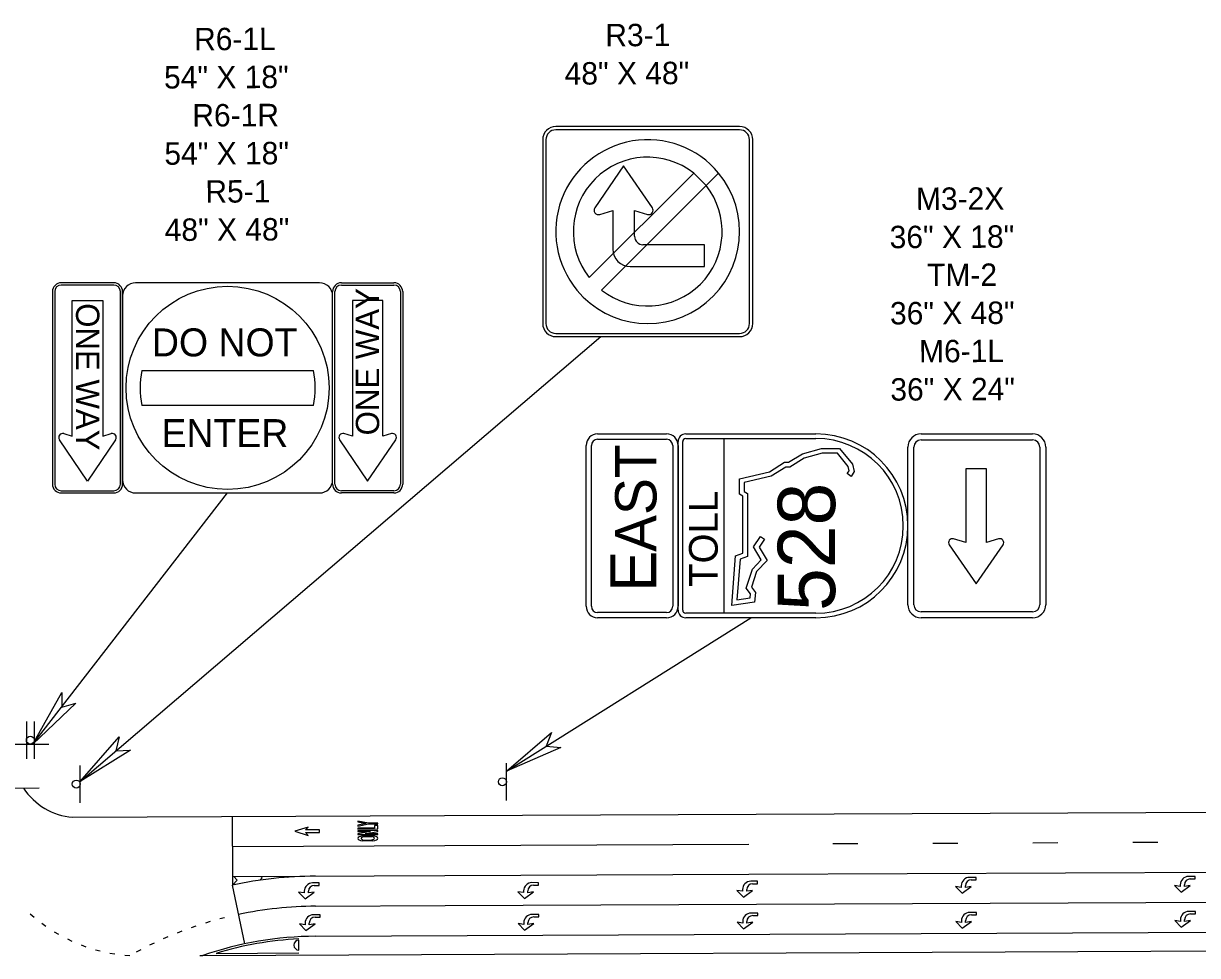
# Model space of a CAD drawing. Extents: x 582908 to 586039, y 1530940 to 1532988.
# Drawn here: x 583736 to 584469, y 1532406 to 1532988 of the extents above; entities that cross this region are included whole.
import ezdxf

# ---------------------------------------------------------------- set-up
doc = ezdxf.new("R2010")
doc.units = 0
for name, color, linetype in [('DirArrowsPavt', 7, 'Continuous'), ('LeaderLine_dp', 7, 'Continuous'), ('PavtMessage', 7, 'Continuous'), ('PMStripe12W', 7, 'Continuous'), ('PMStripe18W', 7, 'Continuous'), ('PMStripe24W', 7, 'Continuous'), ('PMStripe6W', 7, 'Continuous'), ('PMStripe6W(10-30)', 7, 'Continuous'), ('PMStripe6W(2-4)', 7, 'Continuous'), ('PMStripe6Y', 7, 'Continuous'), ('PMStripe6Y(2-4)', 7, 'Continuous'), ('PMStripe8W', 7, 'Continuous'), ('SignPanel', 7, 'Continuous'), ('SignSupport', 7, 'Continuous'), ('TextLabel', 7, 'Continuous')]:
    doc.layers.add(name, color=color, linetype=linetype)

msp = doc.modelspace()

# ---------------------------------------------------------------- linework, layer by layer
at = {"layer": 'DirArrowsPavt'}
for p, q in [((583913.26, 1532486.2), (583905.07, 1532483.56)), ((583911.71, 1532484.37), (583913.26, 1532486.2)), ((583920.43, 1532484.41), (583911.71, 1532484.37)), ((583920.44, 1532482.85), (583920.43, 1532484.41)), ((583905.07, 1532483.56), (583913.28, 1532480.99)), ((583911.71, 1532482.81), (583920.44, 1532482.85)), ((583913.28, 1532480.99), (583911.71, 1532482.81))]:
    msp.add_line(p, q, dxfattribs=at)
for points in [[(584327.57, 1532453.21), (584330.7, 1532453.2), (584330.7, 1532454.77), (584326.53, 1532454.77)], [(584464.38, 1532453.82), (584467.5, 1532453.81), (584467.51, 1532455.37), (584463.34, 1532455.38)], [(583917.18, 1532449.72), (583920.31, 1532449.72), (583920.31, 1532451.28), (583916.15, 1532451.29)], [(584054.17, 1532449.89), (584057.29, 1532449.89), (584057.29, 1532451.45), (584053.13, 1532451.46)], [(584184.68, 1532447.12), (584184.68, 1532446.08), (584181.16, 1532446.6), (584185.19, 1532442.43)], [(584185.19, 1532442.43), (584190.93, 1532446.59), (584187.28, 1532446.07), (584187.28, 1532447.12)], [(584190.93, 1532450.75), (584194.06, 1532450.75), (584194.06, 1532452.31), (584189.9, 1532452.32)], [(584321.32, 1532449.57), (584321.32, 1532448.53), (584317.8, 1532449.06), (584321.83, 1532444.89)], [(584321.83, 1532444.89), (584327.57, 1532449.04), (584323.92, 1532448.53), (584323.92, 1532449.57)], [(584458.12, 1532450.18), (584458.12, 1532449.14), (584454.6, 1532449.67), (584458.63, 1532445.49)], [(584458.63, 1532445.49), (584464.37, 1532449.65), (584460.72, 1532449.13), (584460.73, 1532450.18)], [(583910.93, 1532446.09), (583910.93, 1532445.05), (583907.41, 1532445.57), (583911.44, 1532441.4)], [(583911.44, 1532441.4), (583917.18, 1532445.56), (583913.53, 1532445.04), (583913.53, 1532446.09)], [(584047.91, 1532446.26), (584047.91, 1532445.22), (584044.39, 1532445.74), (584048.42, 1532441.57)], [(584048.42, 1532441.57), (584054.16, 1532445.73), (584050.51, 1532445.21), (584050.51, 1532446.25)], [(584191.02, 1532430.92), (584194.15, 1532430.91), (584194.15, 1532432.48), (584189.98, 1532432.48)], [(584327.67, 1532431.35), (584330.8, 1532431.34), (584330.8, 1532432.9), (584326.63, 1532432.91)], [(584464.47, 1532431.95), (584467.6, 1532431.95), (584467.6, 1532433.51), (584463.44, 1532433.52)], [(583911.41, 1532426.25), (583911.4, 1532425.21), (583907.89, 1532425.74), (583911.92, 1532421.57)], [(583911.92, 1532421.57), (583917.65, 1532425.72), (583914.01, 1532425.21), (583914.01, 1532426.25)], [(583917.66, 1532429.89), (583920.79, 1532429.88), (583920.79, 1532431.45), (583916.62, 1532431.45)], [(584048, 1532426.42), (584048, 1532425.38), (584044.48, 1532425.91), (584048.51, 1532421.73)], [(584048.51, 1532421.73), (584054.25, 1532425.89), (584050.6, 1532425.38), (584050.6, 1532426.42)], [(584054.25, 1532430.06), (584057.38, 1532430.05), (584057.38, 1532431.61), (584053.21, 1532431.62)], [(584184.77, 1532427.28), (584184.76, 1532426.24), (584181.25, 1532426.77), (584185.28, 1532422.6)], [(584185.28, 1532422.6), (584191.02, 1532426.75), (584187.37, 1532426.24), (584187.37, 1532427.28)], [(584321.41, 1532427.71), (584321.41, 1532426.67), (584317.9, 1532427.2), (584321.93, 1532423.02)], [(584321.93, 1532423.02), (584327.66, 1532427.18), (584324.02, 1532426.66), (584324.02, 1532427.71)], [(584458.22, 1532428.32), (584458.22, 1532427.28), (584454.7, 1532427.8), (584458.73, 1532423.63)], [(584458.73, 1532423.63), (584464.47, 1532427.79), (584460.82, 1532427.27), (584460.82, 1532428.31)]]:
    msp.add_lwpolyline(points, dxfattribs=at)
for centre, radius in [((584326.53, 1532449.57), 5.21), ((584463.33, 1532450.17), 5.21), ((583916.14, 1532446.08), 5.21), ((583917.18, 1532446.08), 3.65), ((584053.12, 1532446.25), 5.21), ((584054.16, 1532446.25), 3.65), ((584189.89, 1532447.11), 5.21), ((584190.93, 1532447.11), 3.65), ((584327.57, 1532449.56), 3.65), ((584464.37, 1532450.17), 3.65), ((584189.97, 1532427.28), 5.21), ((584326.62, 1532427.7), 5.21), ((584463.43, 1532428.31), 5.21), ((583916.61, 1532426.24), 5.21), ((583917.66, 1532426.24), 3.65), ((584053.21, 1532426.41), 5.21), ((584054.25, 1532426.41), 3.65), ((584191.02, 1532427.27), 3.65), ((584327.66, 1532427.7), 3.65), ((584464.47, 1532428.31), 3.65)]:
    msp.add_arc(centre, radius, 89.90326, 179.90326, dxfattribs=at)
at = {"layer": 'LeaderLine_dp'}
for p, q in [((583770.98, 1532514.7), (584096.08, 1532792.5)), ((583741.46, 1532537.97), (583863.01, 1532694.88)), ((584037.19, 1532521.1), (584189.87, 1532616.9)), ((583741.46, 1532537.97), (583759.52, 1532570.24)), ((583759.52, 1532570.24), (583759.38, 1532561.1)), ((583768.2, 1532563.52), (583741.46, 1532537.97)), ((583759.38, 1532561.1), (583768.2, 1532563.52)), ((583770.98, 1532514.7), (583795.22, 1532542.63)), ((583795.22, 1532542.63), (583793.22, 1532533.71)), ((584037.19, 1532521.1), (584065.26, 1532545.19)), ((584065.26, 1532545.19), (584061.97, 1532536.65)), ((584071.09, 1532535.89), (584037.19, 1532521.1)), ((584061.97, 1532536.65), (584071.09, 1532535.89)), ((583802.35, 1532534.29), (583770.98, 1532514.7)), ((583793.22, 1532533.71), (583802.35, 1532534.29))]:
    msp.add_line(p, q, dxfattribs=at)
at = {"layer": 'PavtMessage'}
for p, q in [((583951.07, 1532488.65), (583944.29, 1532489.92)), ((583944.29, 1532489.92), (583944.3, 1532489.39)), ((583944.3, 1532489.39), (583949.67, 1532488.38)), ((583949.67, 1532488.38), (583944.31, 1532487.33)), ((583944.31, 1532486.8), (583951.07, 1532488.13)), ((583944.31, 1532487.33), (583944.31, 1532486.8)), ((583954.73, 1532485.54), (583944.31, 1532485.49)), ((583944.31, 1532485.49), (583944.32, 1532484.97)), ((583944.32, 1532484.97), (583956.82, 1532485.03)), ((583956.82, 1532483.99), (583944.32, 1532483.93)), ((583944.32, 1532483.93), (583944.32, 1532483.41)), ((583956.8, 1532488.67), (583951.07, 1532488.65)), ((583951.07, 1532488.13), (583956.8, 1532488.15)), ((583956.81, 1532487.11), (583954.72, 1532487.1)), ((583954.72, 1532487.1), (583954.73, 1532485.54)), ((583956.8, 1532488.15), (583956.8, 1532488.67)), ((583956.82, 1532485.03), (583956.81, 1532487.11)), ((583956.82, 1532483.47), (583956.82, 1532483.99)), ((583944.32, 1532483.41), (583952.29, 1532483.45)), ((583952.29, 1532483.45), (583944.33, 1532481.98)), ((583944.33, 1532481.98), (583944.33, 1532481.46)), ((583944.33, 1532481.46), (583956.83, 1532481.51)), ((583947.37, 1532480.69), (583953.8, 1532480.72)), ((583953.82, 1532477.59), (583947.38, 1532477.57)), ((583953.09, 1532480.19), (583948.09, 1532480.17)), ((583948.1, 1532478.09), (583953.1, 1532478.11)), ((583949.02, 1532482), (583956.82, 1532483.47)), ((583956.83, 1532482.03), (583949.02, 1532482)), ((583956.83, 1532481.51), (583956.83, 1532482.03))]:
    msp.add_line(p, q, dxfattribs=at)
for major_axis, ratio, start_param, end_param in [((-6.25, -0.03), 0.291667, 5.253489, 7.312882), ((-4.17, -0.02), 0.3125, 5.35589, 7.210481), ((-4.17, -0.02), 0.3125, 2.214297, 4.068888), ((-6.25, -0.03), 0.291667, 2.111896, 4.171289)]:
    msp.add_ellipse((583950.59, 1532479.14), major_axis=major_axis, ratio=ratio, start_param=start_param, end_param=end_param, dxfattribs=at)
at = {"layer": 'PMStripe12W'}
msp.add_line((583570.9, 1532509.82), (583745.38, 1532510.59), dxfattribs=at)
at = {"layer": 'PMStripe18W'}
for p, q in [((583866.83, 1532455.27), (583869.07, 1532453.05)), ((583883.2, 1532452.98), (583884.68, 1532454.47)), ((583883.81, 1532455.34), (583884.68, 1532454.47)), ((583899.92, 1532454.78), (583900.31, 1532455.18)), ((583900.06, 1532455.42), (583900.31, 1532455.18)), ((583865.99, 1532449.94), (583869.07, 1532453.05))]:
    msp.add_line(p, q, dxfattribs=at)
at = {"layer": 'PMStripe24W'}
for p, q in [((583865.89, 1532492.76), (583866.06, 1532455.26)), ((583873.75, 1532413.26), (583865.99, 1532449.94))]:
    msp.add_line(p, q, dxfattribs=at)
at = {"layer": 'PMStripe6W'}
for p, q in [((583866.32, 1532474.02), (583998.69, 1532474.6)), ((583998.69, 1532474.6), (584188.53, 1532475.44)), ((583866.06, 1532455.26), (583998.77, 1532455.85)), ((583998.77, 1532455.85), (584188.62, 1532456.69)), ((584188.62, 1532456.69), (584842.51, 1532459.59)), ((583998.86, 1532437.1), (584764.47, 1532440.5)), ((583917.99, 1532436.74), (583998.86, 1532437.1))]:
    msp.add_line(p, q, dxfattribs=at)
msp.add_arc((583919.04, 1532199.25), 237.5, 90.25398, 101.94955, dxfattribs=at)
at = {"layer": 'PMStripe6W(10-30)'}
for p, q in [((584444.16, 1532476.58), (584428.54, 1532476.51)), ((584256.67, 1532475.75), (584241.04, 1532475.68)), ((584319.16, 1532476.02), (584303.54, 1532475.95)), ((584381.66, 1532476.3), (584366.04, 1532476.23))]:
    msp.add_line(p, q, dxfattribs=at)
at = {"layer": 'PMStripe6W(2-4)'}
for p, q in [((583852.12, 1532427.12), (583849.12, 1532426.22)), ((583861.16, 1532429.59), (583858.14, 1532428.8)), ((583834.35, 1532421.13), (583831.44, 1532420)), ((583843.18, 1532424.3), (583840.22, 1532423.29)), ((583817.12, 1532413.76), (583814.3, 1532412.4)), ((583825.66, 1532417.62), (583822.8, 1532416.37)), ((583808.73, 1532409.58), (583805.97, 1532408.11))]:
    msp.add_line(p, q, dxfattribs=at)
at = {"layer": 'PMStripe6Y'}
for p, q in [((583918.07, 1532417.99), (584815.89, 1532421.97)), ((583847.49, 1532405.96), (584975.54, 1532410.96)), ((583907.57, 1532409.35), (583907.54, 1532415.6)), ((583855.82, 1532407.3), (583907.58, 1532407.53))]:
    msp.add_line(p, q, dxfattribs=at)
for centre, radius, start, end in [((583919.04, 1532199.25), 218.75, 90.25398, 109.09317), ((583919.04, 1532199.25), 217.45, 93.04198, 106.90179), ((583907.56, 1532412.48), 3.12, 90.25398, 270.25398)]:
    msp.add_arc(centre, radius, start, end, dxfattribs=at)
at = {"layer": 'PMStripe6Y(2-4)'}
for p, q in [((583739.77, 1532432.05), (583742.12, 1532429.99)), ((583747, 1532426.09), (583749.53, 1532424.25)), ((583754.75, 1532420.82), (583757.44, 1532419.22)), ((583762.95, 1532416.29), (583765.77, 1532414.95)), ((583771.54, 1532412.53), (583774.47, 1532411.45)), ((583780.43, 1532409.58), (583783.45, 1532408.78)), ((583789.56, 1532407.46), (583792.64, 1532406.94)), ((583798.85, 1532406.19), (583801.96, 1532405.96)), ((583845.71, 1532405.96), (583847.49, 1532405.96))]:
    msp.add_line(p, q, dxfattribs=at)
at = {"layer": 'PMStripe8W'}
for p, q in [((583766.26, 1532492.32), (583998.61, 1532493.35)), ((583998.61, 1532493.35), (584975.15, 1532497.68)), ((583866.06, 1532455.26), (583865.99, 1532449.94))]:
    msp.add_line(p, q, dxfattribs=at)
for centre, radius, start, end in [((583769.45, 1532532.69), 40.5, 213.15386, 265.48722), ((583919.04, 1532199.25), 256.25, 90.25398, 101.94955)]:
    msp.add_arc(centre, radius, start, end, dxfattribs=at)
at = {"layer": 'SignPanel'}
for p, q in [((584182.87, 1532923.75), (584068.03, 1532923.75)), ((584182.87, 1532921.7), (584068.03, 1532921.7)), ((584059.83, 1532915.55), (584059.83, 1532800.71)), ((584061.88, 1532915.55), (584061.88, 1532800.71)), ((584189.02, 1532800.71), (584189.02, 1532915.55)), ((584191.07, 1532800.71), (584191.07, 1532915.55)), ((584088.94, 1532829.36), (584154.22, 1532894.63)), ((584110.41, 1532899.14), (584092.44, 1532873.01)), ((584128.39, 1532873.01), (584110.41, 1532899.14)), ((584161.96, 1532886.9), (584154.22, 1532894.63)), ((584161.96, 1532886.9), (584169.74, 1532894.68)), ((584161.96, 1532886.9), (584096.68, 1532821.62)), ((584095.5, 1532868.85), (584103.57, 1532871.37)), ((584103.57, 1532871.37), (584103.57, 1532847.19)), ((584117.25, 1532855.18), (584117.25, 1532871.37)), ((584117.25, 1532871.37), (584125.32, 1532868.85)), ((584161, 1532849.93), (584122.5, 1532849.93)), ((584161, 1532836.25), (584161, 1532849.93)), ((584114.51, 1532836.25), (584161, 1532836.25)), ((583791.92, 1532826.13), (583759.1, 1532826.13)), ((583791.92, 1532824.76), (583759.1, 1532824.76)), ((583920.43, 1532826.13), (583805.59, 1532826.13)), ((583934.1, 1532826.13), (583966.92, 1532826.13)), ((583934.1, 1532824.76), (583966.92, 1532824.76)), ((583753.64, 1532820.66), (583753.64, 1532700.35)), ((583755, 1532820.66), (583755, 1532700.35)), ((583765.94, 1532730.43), (583765.94, 1532815.19)), ((583765.94, 1532815.19), (583785.08, 1532815.19)), ((583785.08, 1532815.19), (583785.08, 1532730.43)), ((583796.02, 1532700.35), (583796.02, 1532820.66)), ((583797.39, 1532700.35), (583797.39, 1532820.66)), ((583797.39, 1532817.93), (583797.39, 1532703.08)), ((583928.64, 1532700.35), (583928.64, 1532820.66)), ((583928.64, 1532703.08), (583928.64, 1532817.93)), ((583930, 1532700.35), (583930, 1532820.66)), ((583960.08, 1532815.19), (583940.94, 1532815.19)), ((583940.94, 1532815.19), (583940.94, 1532730.43)), ((583960.08, 1532730.43), (583960.08, 1532815.19)), ((583971.02, 1532820.66), (583971.02, 1532700.35)), ((583972.39, 1532820.66), (583972.39, 1532700.35)), ((584068.03, 1532794.55), (584182.87, 1532794.55)), ((584068.03, 1532792.5), (584182.87, 1532792.5)), ((583809.43, 1532771.44), (583916.59, 1532771.44)), ((583916.59, 1532749.57), (583809.43, 1532749.57)), ((583775.51, 1532702.17), (583757.94, 1532728.11)), ((583760.71, 1532731.93), (583765.94, 1532730.43)), ((583793.08, 1532728.11), (583775.51, 1532702.17)), ((583785.08, 1532730.43), (583790.32, 1532731.93)), ((583932.94, 1532728.11), (583950.51, 1532702.17)), ((583940.94, 1532730.43), (583935.7, 1532731.93)), ((583950.51, 1532702.17), (583968.08, 1532728.11)), ((583965.32, 1532731.93), (583960.08, 1532730.43)), ((584213.29, 1532714.01), (584222.08, 1532719.34)), ((584222.08, 1532719.34), (584234.1, 1532722.63)), ((584234.5, 1532719.64), (584223.27, 1532716.57)), ((584234.1, 1532722.63), (584245.33, 1532722.63)), ((584243.91, 1532719.64), (584234.5, 1532719.64)), ((584250.61, 1532711.47), (584243.91, 1532719.64)), ((584245.33, 1532722.63), (584253.36, 1532712.84)), ((584201.42, 1532708.11), (584210.9, 1532714.01)), ((584211.76, 1532711.02), (584202.58, 1532705.31)), ((584210.9, 1532714.01), (584213.29, 1532714.01)), ((584214.13, 1532711.02), (584211.76, 1532711.02)), ((584223.27, 1532716.57), (584214.13, 1532711.02)), ((584251.25, 1532708.79), (584250.61, 1532711.47)), ((584253.36, 1532712.84), (584254.47, 1532708.18)), ((584182.78, 1532703.78), (584201.42, 1532708.11)), ((584182.78, 1532694.21), (584182.78, 1532703.78)), ((584202.58, 1532705.31), (584185.77, 1532701.4)), ((584249.97, 1532706.94), (584251.25, 1532708.79)), ((584252.43, 1532705.23), (584249.97, 1532706.94)), ((584254.47, 1532708.18), (584252.43, 1532705.23)), ((584324.13, 1532709.99), (584324.13, 1532663.94)), ((584337.05, 1532709.99), (584324.13, 1532709.99)), ((584337.05, 1532663.94), (584337.05, 1532709.99)), ((584185.77, 1532701.4), (584185.77, 1532695.8)), ((583759.1, 1532696.25), (583791.92, 1532696.25)), ((583759.1, 1532694.88), (583791.92, 1532694.88)), ((583805.59, 1532694.88), (583920.43, 1532694.88)), ((583966.92, 1532696.25), (583934.1, 1532696.25)), ((583966.92, 1532694.88), (583934.1, 1532694.88)), ((584184.76, 1532692.87), (584182.78, 1532694.21)), ((584184.76, 1532657.3), (584184.76, 1532692.87)), ((584185.77, 1532695.8), (584187.75, 1532694.46)), ((584187.75, 1532694.46), (584187.75, 1532655.25)), ((584191.59, 1532661.15), (584195.97, 1532667.63)), ((584195.97, 1532667.63), (584198.45, 1532665.95)), ((584196.27, 1532653.19), (584191.59, 1532661.15)), ((584198.45, 1532665.95), (584195.12, 1532661.04)), ((584195.12, 1532661.04), (584199.97, 1532652.78)), ((584313.8, 1532662.46), (584330.59, 1532638.01)), ((584324.13, 1532663.94), (584316.53, 1532666.21)), ((584330.59, 1532638.01), (584347.38, 1532662.46)), ((584344.65, 1532666.21), (584337.05, 1532663.94)), ((584177.91, 1532624.55), (584180.3, 1532655.56)), ((584180.3, 1532655.56), (584184.76, 1532657.3)), ((584183.14, 1532653.46), (584181.18, 1532628.09)), ((584187.75, 1532655.25), (584183.14, 1532653.46)), ((584190.83, 1532647.32), (584196.27, 1532653.19)), ((584199.97, 1532652.78), (584193.47, 1532645.76)), ((584186.93, 1532635.35), (584190.83, 1532647.32)), ((584193.47, 1532645.76), (584190.27, 1532635.94)), ((584189.71, 1532631.83), (584186.93, 1532635.35)), ((584189.4, 1532629.37), (584189.71, 1532631.83)), ((584190.27, 1532635.94), (584192.83, 1532632.7)), ((584192.83, 1532632.7), (584192.09, 1532626.76)), ((584192.09, 1532626.76), (584177.91, 1532624.55)), ((584181.18, 1532628.09), (584189.4, 1532629.37))]:
    msp.add_line(p, q, dxfattribs=at)
for points in [[(584094.17, 1532731.74), (584137.24, 1532731.74)], [(584094.17, 1532728.45), (584137.24, 1532728.45)], [(584144.41, 1532621.68), (584144.41, 1532726.95)], [(584147.28, 1532621.68), (584147.28, 1532726.95)], [(584149.2, 1532731.74), (584230.55, 1532731.74)], [(584149.2, 1532728.87), (584230.55, 1532728.87)], [(584173.12, 1532619.77), (584173.12, 1532728.87)], [(584296.17, 1532731.74), (584365.9, 1532731.74)], [(584296.17, 1532727.98), (584365.9, 1532727.98)], [(584086.99, 1532624.07), (584086.99, 1532724.56)], [(584090.28, 1532624.07), (584090.28, 1532724.56)], [(584141.12, 1532724.56), (584141.12, 1532624.07)], [(584144.41, 1532724.56), (584144.41, 1532624.07)], [(584287.97, 1532625.1), (584287.97, 1532723.54)], [(584291.73, 1532625.1), (584291.73, 1532723.54)], [(584370.34, 1532723.54), (584370.34, 1532625.1)], [(584374.1, 1532723.54), (584374.1, 1532625.1)], [(584137.24, 1532620.19), (584094.17, 1532620.19)], [(584137.24, 1532616.9), (584094.17, 1532616.9)], [(584230.55, 1532619.77), (584149.2, 1532619.77)], [(584230.55, 1532616.9), (584149.2, 1532616.9)], [(584365.9, 1532620.66), (584296.17, 1532620.66)], [(584365.9, 1532616.9), (584296.17, 1532616.9)]]:
    msp.add_lwpolyline(points, dxfattribs=at)
msp.add_circle((583863.01, 1532760.5), 63.44, dxfattribs=at)
for centre, radius, start, end in [((584068.03, 1532915.55), 8.2, 90, 180), ((584182.87, 1532915.55), 8.2, 360, 90), ((584068.03, 1532915.55), 6.15, 90, 180), ((584182.87, 1532915.55), 6.15, 360, 90), ((584125.45, 1532858.13), 57.42, 39.53499, 219.53501), ((584125.45, 1532858.13), 46.48, 51.75662, 218.24339), ((584125.45, 1532858.13), 57.42, 219.53501, 39.53499), ((584125.45, 1532858.13), 46.48, 231.75662, 38.24337), ((584094.69, 1532871.46), 2.73, 145.48536, 287.36264), ((584126.13, 1532871.46), 2.73, 252.63736, 34.51464), ((584122.5, 1532855.18), 5.25, 180, 270), ((584114.51, 1532847.19), 10.94, 180, 270), ((583759.1, 1532820.66), 5.47, 90, 180), ((583759.1, 1532820.66), 4.1, 90, 180), ((583791.92, 1532820.66), 5.47, 360, 90), ((583791.92, 1532820.66), 4.1, 360, 90), ((583805.59, 1532817.93), 8.2, 90, 180), ((583920.43, 1532817.93), 8.2, 360, 90), ((583934.1, 1532820.66), 5.47, 90, 180), ((583934.1, 1532820.66), 4.1, 90, 180), ((583966.92, 1532820.66), 5.47, 360, 90), ((583966.92, 1532820.66), 4.1, 360, 90), ((584068.03, 1532800.71), 8.2, 180, 270), ((584068.03, 1532800.71), 6.15, 180, 270), ((584182.87, 1532800.71), 6.15, 270, 360), ((584182.87, 1532800.71), 8.2, 270, 360), ((583863.01, 1532760.5), 54.69, 168.46307, 191.53692), ((583863.01, 1532760.5), 54.69, 348.46307, 11.53692), ((583760.02, 1532729.52), 2.51, 74.04541, 214.13318), ((583791.01, 1532729.52), 2.51, 325.88703, 105.93889), ((583935.02, 1532729.52), 2.51, 74.06111, 214.11297), ((583966.01, 1532729.52), 2.51, 325.86682, 105.95459), ((584094.17, 1532724.56), 7.18, 90, 180), ((584094.17, 1532724.56), 3.89, 90, 180), ((584137.24, 1532724.56), 7.18, 0, 90), ((584137.24, 1532724.56), 3.89, 0, 90), ((584149.2, 1532726.95), 4.79, 90, 180), ((584149.2, 1532726.95), 1.91, 90, 180), ((584230.55, 1532674.32), 57.42, 270, 90), ((584230.55, 1532674.32), 54.55, 270, 90), ((584296.17, 1532723.54), 8.2, 90, 180), ((584296.17, 1532723.54), 4.44, 90.0544, 180), ((584365.9, 1532723.54), 8.2, 360, 90), ((584365.9, 1532723.54), 4.44, 360, 90), ((583759.1, 1532700.35), 5.47, 180, 270), ((583759.1, 1532700.35), 4.1, 180, 270), ((583791.92, 1532700.35), 5.47, 270, 360), ((583791.92, 1532700.35), 4.1, 270, 360), ((583805.59, 1532703.08), 8.2, 180, 270), ((583920.43, 1532703.08), 8.2, 270, 360), ((583934.1, 1532700.35), 5.47, 180, 270), ((583934.1, 1532700.35), 4.1, 180, 270), ((583966.92, 1532700.35), 4.1, 270, 360), ((583966.92, 1532700.35), 5.47, 270, 360), ((584315.82, 1532663.85), 2.46, 73.35571, 214.48807), ((584345.36, 1532663.85), 2.46, 325.51192, 106.64431), ((584094.17, 1532624.07), 7.18, 180, 270), ((584094.17, 1532624.07), 3.89, 180, 270), ((584137.24, 1532624.07), 7.18, 270, 0), ((584137.24, 1532624.07), 3.89, 270, 0), ((584296.17, 1532625.1), 8.2, 180, 270), ((584296.17, 1532625.1), 4.44, 180, 269.9456), ((584365.9, 1532625.1), 8.2, 270, 360), ((584365.9, 1532625.1), 4.44, 270, 360), ((584149.2, 1532621.68), 4.79, 180, 270), ((584149.2, 1532621.68), 1.91, 180, 270)]:
    msp.add_arc(centre, radius, start, end, dxfattribs=at)
at = {"layer": 'SignSupport'}
for p, q in [((583737.31, 1532552.1), (583737.31, 1532528.82)), ((583742.29, 1532552.1), (583742.29, 1532528.82)), ((583728.16, 1532537.97), (583751.44, 1532537.97)), ((583770.98, 1532501.4), (583770.98, 1532524.68)), ((584037.19, 1532502.81), (584037.19, 1532526.09))]:
    msp.add_line(p, q, dxfattribs=at)
for centre in [(583739.8, 1532540.46), (583768.48, 1532513.04), (584034.69, 1532514.45)]:
    msp.add_circle(centre, 2.49, dxfattribs=at)

# ---------------------------------------------------------------- texts
at = {"layer": 'SignPanel'}
for s, height, rotation, p in [('ONE WAY', 14.567, 90, (583957.69, 1532730.84)), ('ONE WAY', 14.567, 270, (583768.34, 1532813.4)), ('DO NOT', 17.482, 360, (583815.76, 1532780.19)), ('ENTER', 17.482, 360, (583821.73, 1532723.49)), ('AST', 25.839, 90, (584130.92, 1532658.06)), ('528', 35.889, 90, (584242.52, 1532621.18)), ('TOLL', 17.944, 90, (584169.18, 1532636.2)), ('E', 28.71, 90, (584130.76, 1532633.24))]:
    msp.add_text(s, height=height, rotation=rotation, dxfattribs=at).set_placement(p)
at = {"layer": 'TextLabel'}
for s, p in [('R6-1L', (583842.14, 1532971.34)), ('R3-1', (584098.99, 1532973.82)), ('54" X 18"', (583823.36, 1532947.46)), ('48" X 48"', (584073.59, 1532949.9)), ('R6-1R', (583841.02, 1532923.74)), ('54" X 18"', (583823.57, 1532899.86)), ('R5-1', (583849.18, 1532876.17)), ('M3-2X', (584293.06, 1532871.61)), ('48" X 48"', (583823.78, 1532852.26)), ('36" X 18"', (584276.61, 1532847.73)), ('TM-2', (584300.02, 1532824.04)), ('36" X 48"', (584276.82, 1532800.13)), ('M6-1L', (584294.96, 1532776.41)), ('36" X 24"', (584277.03, 1532752.53))]:
    msp.add_text(s, height=14, rotation=0.25398, dxfattribs=at).set_placement(p)

doc.saveas('drawing.dxf')
